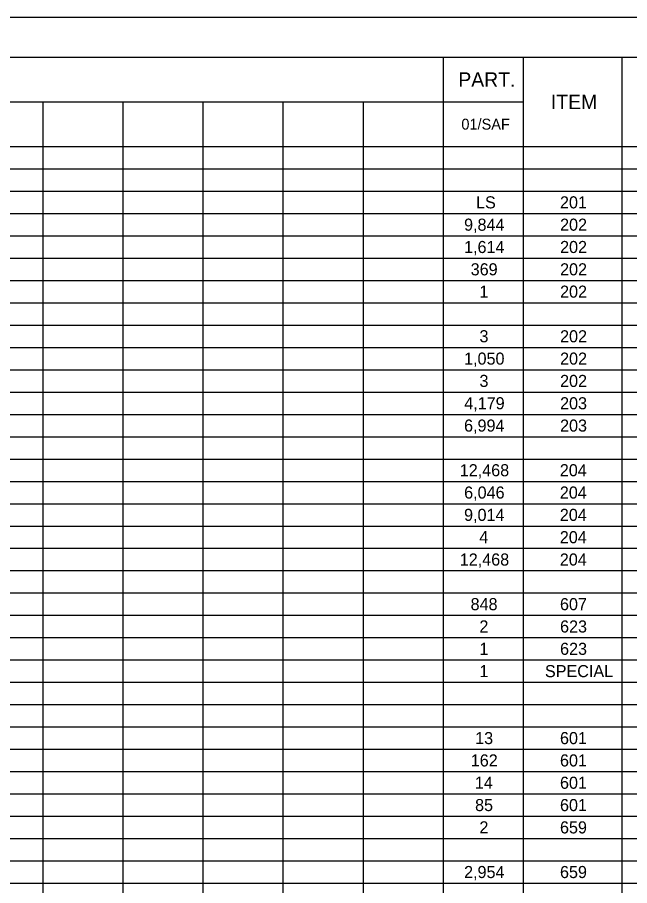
# Model space of a CAD drawing. Extents: x 0 to 34, y 0 to 22.
# Drawn here: x 9.22 to 16.9, y 11.11 to 22 of the extents above; entities that cross this region are included whole.
import ezdxf

# ---------------------------------------------------------------- set-up
doc = ezdxf.new("R2010")
doc.units = 0
for name, color, linetype in [('SH_Border', 7, 'Continuous'), ('SH_Cut_Line', 7, 'Continuous'), ('SH_Text', 7, 'Continuous')]:
    doc.layers.add(name, color=color, linetype=linetype)

msp = doc.modelspace()

# ---------------------------------------------------------------- linework, layer by layer
at = {"layer": 'SH_Border'}
msp.add_lwpolyline([(1.5, 21.5), (33.5, 21.5), (33.5, 0.5), (1.5, 0.5)], close=True, dxfattribs=at)
at = {"layer": 'SH_Cut_Line'}
msp.add_lwpolyline([(0, 0), (34, 0), (34, 22), (0, 22)], close=True, dxfattribs=at)
at = {"layer": 'SH_Text'}
for p, q in [((1.5, 21.5), (32, 21.5)), ((14.56, 21.5), (14.56, 0.5)), ((15.564, 21.5), (15.564, 0.5)), ((16.799, 21.5), (16.799, 0.5)), ((1.5, 20.94), (15.564, 20.94)), ((9.537, 20.94), (9.537, 0.5)), ((10.541, 20.94), (10.541, 0.5)), ((11.546, 20.94), (11.546, 0.5)), ((12.55, 20.94), (12.55, 0.5)), ((13.555, 20.94), (13.555, 0.5)), ((1.5, 20.38), (32, 20.38)), ((1.5, 20.1), (32, 20.1)), ((1.5, 19.82), (32, 19.82)), ((1.5, 19.54), (32, 19.54)), ((1.5, 19.26), (32, 19.26)), ((1.5, 18.98), (32, 18.98)), ((1.5, 18.7), (32, 18.7)), ((1.5, 18.42), (32, 18.42)), ((1.5, 18.14), (32, 18.14)), ((1.5, 17.86), (32, 17.86)), ((1.5, 17.58), (32, 17.58)), ((1.5, 17.3), (32, 17.3)), ((1.5, 17.02), (32, 17.02)), ((1.5, 16.74), (32, 16.74)), ((1.5, 16.46), (32, 16.46)), ((1.5, 16.18), (32, 16.18)), ((1.5, 15.9), (32, 15.9)), ((1.5, 15.62), (32, 15.62)), ((1.5, 15.34), (32, 15.34)), ((1.5, 15.06), (32, 15.06)), ((1.5, 14.78), (32, 14.78)), ((1.5, 14.5), (32, 14.5)), ((1.5, 14.22), (32, 14.22)), ((1.5, 13.94), (32, 13.94)), ((1.5, 13.66), (32, 13.66)), ((1.5, 13.38), (32, 13.38)), ((1.5, 13.1), (32, 13.1)), ((1.5, 12.82), (32, 12.82)), ((1.5, 12.54), (32, 12.54)), ((1.5, 12.26), (32, 12.26)), ((1.5, 11.98), (32, 11.98)), ((1.5, 11.7), (32, 11.7)), ((1.5, 11.42), (32, 11.42)), ((1.5, 11.14), (32, 11.14))]:
    msp.add_line(p, q, dxfattribs=at)

# ---------------------------------------------------------------- texts
for s, height, p in [('PART.', 0.1818, (14.749, 21.129)), ('ITEM', 0.1818, (15.91, 20.849)), ('01/SAF', 0.1364, (14.787, 20.592)), ('LS', 0.1515, (14.971, 19.604)), ('201', 0.1515, (16.024, 19.604)), ('9,844', 0.1515, (14.821, 19.324)), ('202', 0.1515, (16.025, 19.324)), ('1,614', 0.1515, (14.821, 19.044)), ('202', 0.1515, (16.025, 19.044)), ('369', 0.1515, (14.904, 18.764)), ('202', 0.1515, (16.025, 18.764)), ('1', 0.152, (15.013, 18.484)), ('202', 0.1515, (16.025, 18.484)), ('3', 0.152, (15.014, 17.924)), ('202', 0.1515, (16.025, 17.924)), ('1,050', 0.1515, (14.821, 17.644)), ('202', 0.1515, (16.025, 17.644)), ('3', 0.152, (15.014, 17.364)), ('202', 0.1515, (16.025, 17.364)), ('4,179', 0.1515, (14.823, 17.084)), ('203', 0.1515, (16.025, 17.084)), ('6,994', 0.1515, (14.821, 16.804)), ('203', 0.1515, (16.025, 16.804)), ('12,468', 0.1515, (14.767, 16.244)), ('204', 0.1515, (16.022, 16.244)), ('6,046', 0.1515, (14.822, 15.964)), ('204', 0.1515, (16.022, 15.964)), ('9,014', 0.1515, (14.821, 15.684)), ('204', 0.1515, (16.022, 15.684)), ('4', 0.152, (15.011, 15.404)), ('204', 0.1515, (16.022, 15.404)), ('12,468', 0.1515, (14.767, 15.124)), ('204', 0.1515, (16.022, 15.124)), ('848', 0.1515, (14.903, 14.564)), ('607', 0.1515, (16.024, 14.564)), ('2', 0.152, (15.013, 14.284)), ('623', 0.1515, (16.025, 14.284)), ('1', 0.152, (15.013, 14.004)), ('623', 0.1515, (16.025, 14.004)), ('1', 0.152, (15.013, 13.724)), ('SPECIAL', 0.1515, (15.835, 13.724)), ('13', 0.1515, (14.96, 12.884)), ('601', 0.1515, (16.024, 12.884)), ('162', 0.1515, (14.905, 12.604)), ('601', 0.1515, (16.024, 12.604)), ('14', 0.1515, (14.956, 12.324)), ('601', 0.1515, (16.024, 12.324)), ('85', 0.1515, (14.959, 12.044)), ('601', 0.1515, (16.024, 12.044)), ('2', 0.152, (15.013, 11.764)), ('659', 0.1515, (16.024, 11.764)), ('2,954', 0.1515, (14.821, 11.204)), ('659', 0.1515, (16.024, 11.204))]:
    msp.add_text(s, height=height, dxfattribs=at).set_placement(p)

doc.saveas('drawing.dxf')
